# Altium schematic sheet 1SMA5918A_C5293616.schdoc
size 127 x 101 mm
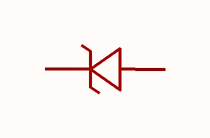
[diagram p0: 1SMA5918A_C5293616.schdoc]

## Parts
D?  1sma5918a_c5293616  [SMA_L4.4-W2.8-LS5.4-RD]  (value not drawn)

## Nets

Not connected (* = marked no-connect by the designer): D? 1(K) 2(A)

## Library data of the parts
D? = 1sma5918a_c5293616: 二极管配置:1个独立式;稳压值(标称值):5.1V;稳压值(范围):4.84V~5.36V;耗散功率(Pd):1.5W;; Manufacturer: CJ(江苏长电/长晶); AddInBom: yes; ModelId: 4f1e9ef2303f48b48aa8ce0cacf8d7b1; ModelTransform: 204.724,102.362,0,0,0,0,0,0,0; Diode Configuration: 1个独立式; Zener Voltage(Nom): 5.1V; Reverse Leakage Current (Ir): 2.5uA@2V; Pd - Power Dissipation: 1.5W; Impedance(Zzt): 4Ω; Impedance(Zzk): 350Ω; Operating Junction Temperature Range: -55℃~+150℃; Tolerance: ±5%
